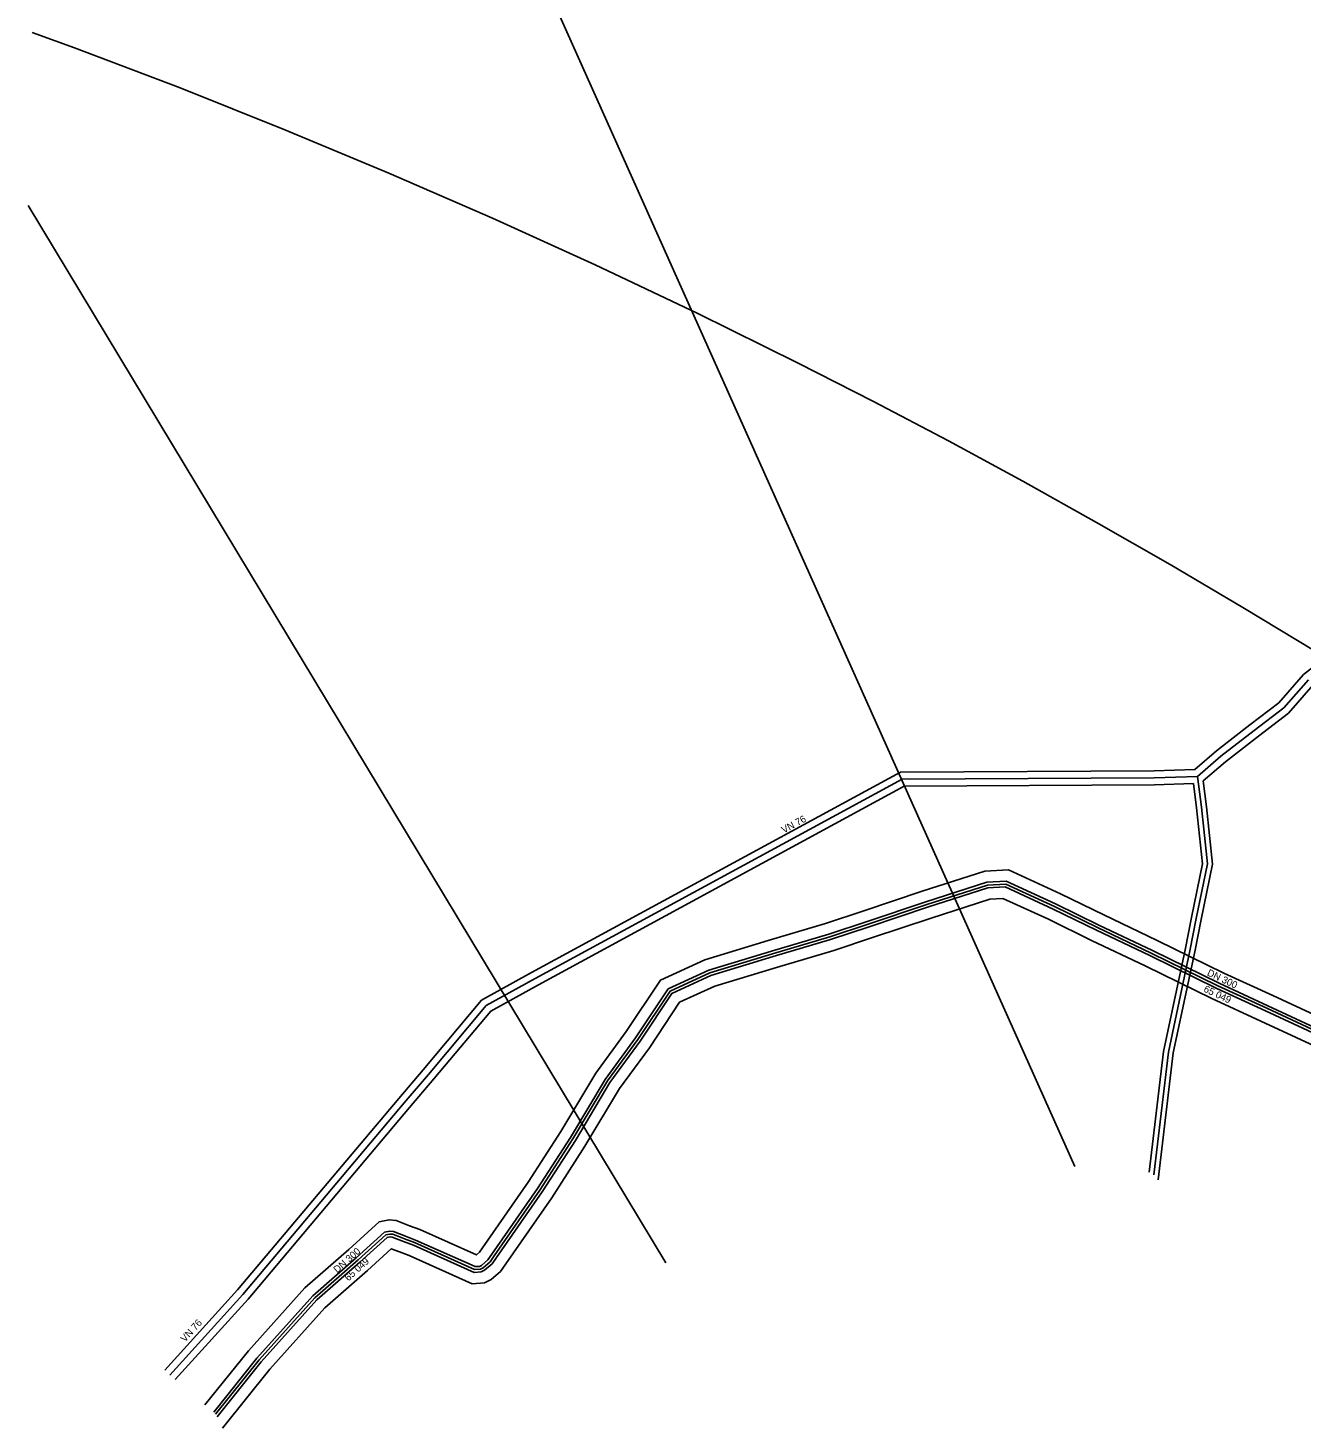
# Model space of a CAD drawing. Extents: x -546883 to -534032, y -1096714 to -1090569.
# Drawn here: x -546883 to -545077, y -1096062 to -1094077 of the extents above; entities that cross this region are included whole.
import ezdxf

# ---------------------------------------------------------------- set-up
doc = ezdxf.new("R2010")
doc.units = 0
for name, color, linetype in [('Vrstva 18', 7, 'Continuous'), ('Vrstva 22', 7, 'Continuous'), ('Vrstva 23', 7, 'Continuous'), ('Vrstva 26', 7, 'Continuous'), ('Vrstva 29', 7, 'Continuous'), ('Vrstva 3', 7, 'Continuous'), ('Vrstva 8', 7, 'Continuous')]:
    doc.layers.add(name, color=color, linetype=linetype)

msp = doc.modelspace()

# ---------------------------------------------------------------- linework, layer by layer
at = {"layer": 'Vrstva 18'}
for points in [[(-542773.7, -1093901.3), (-543058.2, -1093938.1), (-543188.5, -1094052), (-543268, -1094122), (-543394.3, -1094232), (-543480.6, -1094482.6), (-543669.1, -1094560.4), (-543758.5, -1094597.4), (-543910.8, -1094567.9), (-544052.3, -1094495.1), (-544239.4, -1094494), (-544444.1, -1094562), (-544493.4, -1094608), (-544552.5, -1094664), (-544816.5, -1094812.4), (-544839.7, -1094831.7), (-544930, -1094904.6), (-544980.9, -1094945), (-545061.4, -1095007.9), (-545096.6, -1095048), (-545139, -1095080.4), (-545186, -1095116.8), (-545217.5, -1095144)], [(-546689.4, -1095979.6), (-546586.2, -1095865.7), (-546357.7, -1095594.2), (-546323.1, -1095553.8), (-546240.3, -1095454.8), (-546169.3, -1095415.5), (-545646.6, -1095131.6), (-545287.1, -1095129.7), (-545229.2, -1095127.7), (-545198.7, -1095101.3), (-545151.2, -1095064.5), (-545110.3, -1095033.3), (-545075.2, -1094993.3), (-544993.2, -1094929.3), (-544942.5, -1094889), (-544852.4, -1094816.2), (-544827.9, -1094795.9), (-544564.4, -1094647.8), (-544519.5, -1094605.2)], [(-545231.2, -1095147.8), (-545286.7, -1095149.6), (-545641.5, -1095151.6), (-546159.7, -1095433), (-546227.3, -1095470.5), (-546307.8, -1095566.7), (-546342.5, -1095607.1), (-546571.2, -1095878.9), (-546674.4, -1095992.7)], [(-545294.1, -1095698.9), (-545273.7, -1095527.5), (-545243.1, -1095383.5), (-545234.2, -1095337.8), (-545218.5, -1095261.4), (-545226.9, -1095182.2), (-545231.2, -1095147.8)], [(-545217.5, -1095144), (-545213, -1095180.6), (-545204.3, -1095262.1), (-545220.5, -1095340.6), (-545229.4, -1095386.3), (-545259.9, -1095529.8), (-545281.3, -1095709.9)]]:
    msp.add_lwpolyline(points, dxfattribs=at)
at = {"layer": 'Vrstva 22'}
for p, q in [((-545399.4, -1095690.7), (-546455.8, -1093330.2)), ((-545979.2, -1095827.4), (-546883.1, -1094328.1))]:
    msp.add_line(p, q, dxfattribs=at)
at = {"layer": 'Vrstva 23'}
for points in [[(-545068.3, -1095000.6), (-545103.4, -1095040.6), (-545145.1, -1095072.5), (-545192.4, -1095109.1), (-545225.4, -1095137.6), (-545286.9, -1095139.6), (-545644.1, -1095141.6), (-546164.5, -1095424.3), (-546233.8, -1095462.7), (-546315.5, -1095560.2), (-546350.1, -1095600.7), (-546578.7, -1095872.3), (-546682.3, -1095986.6)], [(-545225.4, -1095137.6), (-545220, -1095181.4), (-545211.4, -1095261.7), (-545227.4, -1095339.2), (-545236.3, -1095384.9), (-545266.8, -1095528.7), (-545287.5, -1095702.7)]]:
    msp.add_lwpolyline(points, dxfattribs=at)
at = {"layer": 'Vrstva 26'}
msp.add_lwpolyline([(-546617.3, -1096042), (-546555.5, -1095965.1), (-546476.6, -1095877.1), (-546415.3, -1095823.3), (-546376.1, -1095787.7), (-546370.2, -1095786.5), (-546365.9, -1095786.9), (-546349.6, -1095793.4), (-546335.3, -1095798.7), (-546250.1, -1095836.9), (-546241.8, -1095836.3), (-546238.2, -1095834.4), (-546228.2, -1095825.9), (-546222.5, -1095817.6), (-546157.6, -1095724.3), (-546110.7, -1095651.6), (-546061.7, -1095569.4), (-546018.8, -1095510.8), (-545973.1, -1095442.2), (-545916.8, -1095416.3), (-545828.1, -1095389.3), (-545746.8, -1095365.3), (-545692.4, -1095347.3), (-545609.4, -1095319.5), (-545523.4, -1095291.7), (-545497.4, -1095290.3), (-545428.3, -1095322.2), (-545367.2, -1095352), (-545291.2, -1095388.1), (-545196.6, -1095434.5), (-545127.4, -1095466.4), (-545028, -1095512.8)], dxfattribs=at)
at = {"layer": 'Vrstva 29'}
msp.add_lwpolyline([(-546877.4, -1094083), (-546817.1, -1094104.8), (-546667.6, -1094161.5), (-546519.1, -1094220.7), (-546371.5, -1094282.2), (-546224.9, -1094346), (-546079.4, -1094412.2), (-545934.9, -1094480.7), (-545791.6, -1094551.5), (-545684.8, -1094606), (-545578.7, -1094661.9), (-545473.3, -1094719.1), (-545368.6, -1094777.5), (-545264.5, -1094837.1), (-545161.2, -1094898), (-545058.7, -1094960.1)], dxfattribs=at)
at = {"layer": 'Vrstva 3'}
for points in [[(-546632.3, -1096028.7), (-546570.8, -1095952.1), (-546490.7, -1095862.9), (-546428.6, -1095808.4), (-546385.5, -1095769.2), (-546371.4, -1095766.3), (-546361.2, -1095767.2), (-546342.5, -1095774.7), (-546327.7, -1095780.2), (-546247.6, -1095816.1), (-546243.2, -1095812.4), (-546239, -1095806.2), (-546174.2, -1095713.2), (-546127.7, -1095641.1), (-546078.4, -1095558.3), (-546035.2, -1095499.4), (-545986.6, -1095426.4), (-545923.9, -1095397.6), (-545833.9, -1095370.2), (-545752.8, -1095346.2), (-545698.7, -1095328.4), (-545615.7, -1095300.5), (-545527.1, -1095271.9), (-545493.6, -1095270.1), (-545419.7, -1095304.1), (-545358.5, -1095334), (-545282.5, -1095370.1), (-545188, -1095416.5), (-545119, -1095448.2), (-545020.2, -1095494.3)], [(-545035.8, -1095531.2), (-545135.8, -1095484.5), (-545205.1, -1095452.6), (-545299.9, -1095406.1), (-545375.9, -1095370.1), (-545436.9, -1095340.2), (-545501.3, -1095310.6), (-545519.7, -1095311.6), (-545603.1, -1095338.5), (-545686.1, -1095366.3), (-545740.8, -1095384.4), (-545822.4, -1095408.5), (-545909.7, -1095435.1), (-545959.6, -1095458), (-546002.4, -1095522.3), (-546045, -1095580.4), (-546093.7, -1095662.1), (-546140.9, -1095735.4), (-546206.1, -1095828.9), (-546213.3, -1095839.5), (-546226.9, -1095851), (-546236.1, -1095855.9), (-546253.6, -1095857.2), (-546342.9, -1095817.2), (-546356.8, -1095812), (-546368.2, -1095807.5), (-546402, -1095838.2), (-546462.5, -1095891.3), (-546540.3, -1095978), (-546607.3, -1096061.6)]]:
    msp.add_lwpolyline(points, dxfattribs=at)
at = {"layer": 'Vrstva 8'}
for points in [[(-546619.9, -1096038.9), (-546558.6, -1095962.5), (-546479.4, -1095874.3), (-546418, -1095820.3), (-546378, -1095784), (-546370.5, -1095782.5), (-546365, -1095782.9), (-546348.2, -1095789.6), (-546333.8, -1095795), (-546249.3, -1095832.8), (-546243, -1095832.4), (-546240.5, -1095831), (-546231.2, -1095823.2), (-546225.8, -1095815.3), (-546160.9, -1095722.1), (-546114.1, -1095649.5), (-546065.1, -1095567.2), (-546022.1, -1095508.5), (-545975.8, -1095439), (-545918.2, -1095412.6), (-545829.3, -1095385.5), (-545748, -1095361.4), (-545693.6, -1095343.5), (-545610.7, -1095315.7), (-545524.2, -1095287.8), (-545496.6, -1095286.3), (-545426.6, -1095318.5), (-545365.5, -1095348.4), (-545289.5, -1095384.5), (-545194.8, -1095430.9), (-545125.7, -1095462.8), (-545026.4, -1095509.1)], [(-545029.6, -1095516.5), (-545129.1, -1095470), (-545198.3, -1095438.2), (-545292.9, -1095391.7), (-545368.9, -1095355.6), (-545430, -1095325.8), (-545498.2, -1095294.4), (-545522.7, -1095295.7), (-545608.1, -1095323.3), (-545691.1, -1095351.1), (-545745.6, -1095369.1), (-545827, -1095393.2), (-545915.4, -1095420.1), (-545970.4, -1095445.3), (-546015.5, -1095513.1), (-546058.4, -1095571.6), (-546107.3, -1095653.7), (-546154.2, -1095726.5), (-546219.2, -1095819.8), (-546225.3, -1095828.6), (-546236, -1095837.7), (-546240.7, -1095840.2), (-546250.8, -1095841), (-546336.8, -1095802.4), (-546351.1, -1095797.1), (-546366.8, -1095790.8), (-546370, -1095790.5), (-546374.2, -1095791.4), (-546412.6, -1095826.3), (-546473.8, -1095879.9), (-546552.5, -1095967.6), (-546615.2, -1096045.8)]]:
    msp.add_lwpolyline(points, dxfattribs=at)

# ---------------------------------------------------------------- texts
at = {"layer": 'Vrstva 23'}
for rotation, p in [(28.5092, (-545811.9, -1095218.7)), (47.8126, (-546660.6, -1095940.5))]:
    msp.add_text('VN 76', height=10, rotation=rotation, dxfattribs=at).set_placement(p)
at = {"layer": 'Vrstva 26'}
for s, rotation, p in [('DN 300', 334.614, (-545212.9, -1095419.4)), ('65 049', 334.614, (-545217.8, -1095442.4)), ('DN 300', 41.4386, (-546444.9, -1095842.4)), ('65 049', 42.0178, (-546429, -1095853.9))]:
    msp.add_text(s, height=10, rotation=rotation, dxfattribs=at).set_placement(p)

doc.saveas('drawing.dxf')
